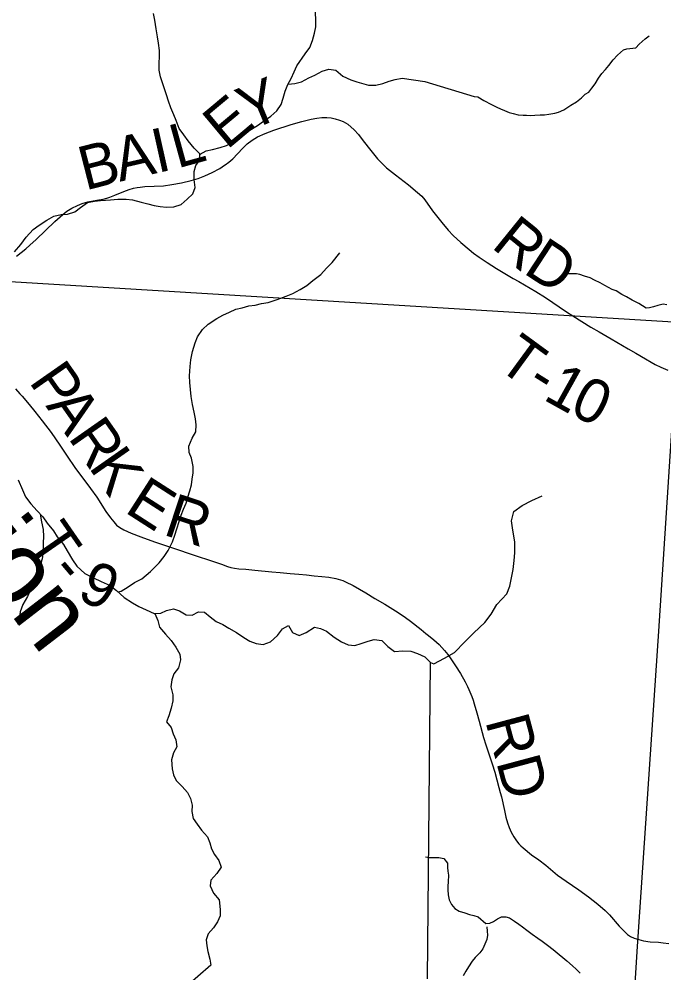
# Model space of a CAD drawing. Extents: x -8.2 to 34, y 0 to 22.
# Drawn here: x 6.76 to 7.595, y 18.744 to 19.98 of the extents above; entities that cross this region are included whole.
import ezdxf

# ---------------------------------------------------------------- set-up
doc = ezdxf.new("R2010")
doc.units = 0
for name, color, linetype in [('GM_X_Corporation', 7, 'Continuous'), ('GM_X_Minor_River', 7, 'Continuous'), ('GM_X_Minor_River_Text', 7, 'Continuous'), ('GM_X_Township_Road', 7, 'Continuous'), ('GM_X_Township_Road_Text', 7, 'Continuous')]:
    doc.layers.add(name, color=color, linetype=linetype)

msp = doc.modelspace()

# ---------------------------------------------------------------- linework, layer by layer
at = {"layer": 'GM_X_Corporation'}
for points in [[(6.6629, 20.6653), (7.6877, 20.6096), (7.6147, 19.5864), (6.5914, 19.6487)], [(7.6147, 19.5864), (8.6299, 19.5206), (8.6049, 19.1351), (8.5816, 18.7383), (8.5636, 18.5025), (7.9912, 18.537), (7.548, 18.5656), (7.5613, 18.7777), (7.5889, 19.1864)]]:
    msp.add_lwpolyline(points, close=True, dxfattribs=at)
at = {"layer": 'GM_X_Minor_River'}
for points in [[(6.9942, 19.8024), (6.9947, 19.8048), (7.0023, 19.809), (7.0106, 19.8109), (7.0205, 19.8133), (7.0285, 19.816), (7.0406, 19.8225), (7.0485, 19.829), (7.0588, 19.8359), (7.069, 19.842), (7.0766, 19.8473), (7.086, 19.8538), (7.094, 19.8611), (7.0993, 19.8691), (7.1023, 19.8775), (7.1045, 19.8862), (7.1082, 19.895), (7.1124, 19.903), (7.1165, 19.9113), (7.1199, 19.9193), (7.1304, 19.9346), (7.1365, 19.943), (7.1402, 19.9521), (7.1428, 19.9616), (7.1443, 19.9696), (7.1441, 19.9969)], [(6.754, 19.6782), (6.7623, 19.6877), (6.7691, 19.6972), (6.7782, 19.7072), (6.7861, 19.7125), (6.796, 19.719), (6.8051, 19.7244), (6.8145, 19.7267), (6.8225, 19.7271), (6.832, 19.7299), (6.8396, 19.7356), (6.8487, 19.7421), (6.8578, 19.744), (6.8654, 19.7445), (6.8783, 19.7457), (6.8878, 19.7465), (6.8988, 19.7465), (6.9068, 19.7454), (6.9179, 19.7425), (6.9266, 19.7402), (6.935, 19.7384), (6.9426, 19.7369), (6.951, 19.7362), (6.9605, 19.7366), (6.97, 19.7393), (6.9775, 19.7462), (6.9851, 19.7534), (6.9881, 19.7614), (6.9869, 19.7721), (6.9868, 19.7823), (6.9887, 19.7899), (6.994, 19.7975), (6.9943, 19.8051), (6.9867, 19.8127), (6.979, 19.8218), (6.9733, 19.8297), (6.9675, 19.838), (6.9636, 19.8483), (6.9606, 19.8558), (6.9567, 19.8649), (6.9536, 19.8733), (6.9509, 19.8816), (6.9482, 19.8892), (6.9459, 19.8971), (6.9432, 19.9051), (6.9416, 19.9135), (6.9412, 19.9229), (6.9419, 19.9309), (6.9418, 19.9393), (6.9406, 19.9488), (6.9391, 19.9567), (6.9375, 19.967), (6.9359, 19.9783), (6.9339, 19.9871)], [(7.2858, 19.8988), (7.3494, 19.8794), (7.3543, 19.879), (7.3623, 19.8742), (7.3719, 19.8693), (7.3791, 19.8656), (7.3837, 19.8633), (7.389, 19.8615), (7.3948, 19.8589), (7.4001, 19.8574), (7.4066, 19.8556), (7.413, 19.8553), (7.4176, 19.8553), (7.4225, 19.855), (7.4282, 19.8554), (7.435, 19.8558), (7.4407, 19.8559), (7.4464, 19.8567), (7.454, 19.8579), (7.4589, 19.8591), (7.4657, 19.8622), (7.4747, 19.8684), (7.4823, 19.8726), (7.4887, 19.8776), (7.4936, 19.8826), (7.4981, 19.8853), (7.5022, 19.8903), (7.5063, 19.896), (7.5108, 19.9033), (7.5149, 19.9094), (7.5198, 19.9144), (7.5243, 19.9198), (7.5299, 19.927), (7.5355, 19.9332), (7.5431, 19.9401), (7.5476, 19.9413), (7.559, 19.9425), (7.5635, 19.9475), (7.571, 19.9544), (7.5763, 19.9583)], [(7.1084, 19.8953), (7.1174, 19.8962), (7.1257, 19.8985), (7.1352, 19.9035), (7.1431, 19.9073), (7.1526, 19.9123), (7.1614, 19.915), (7.1705, 19.9135), (7.1793, 19.906), (7.1896, 19.9011), (7.1976, 19.8985), (7.2128, 19.894), (7.2223, 19.8941), (7.2314, 19.8964), (7.2394, 19.8995), (7.2474, 19.9014), (7.2561, 19.9034), (7.2858, 19.8988)], [(6.8878, 19.2377), (6.8923, 19.2385), (6.9014, 19.2438), (6.9093, 19.2496), (6.9188, 19.2542), (6.9302, 19.2637), (6.9415, 19.2752), (6.9479, 19.2832), (6.9532, 19.2912), (6.9585, 19.3022), (6.9618, 19.311), (6.9644, 19.319), (6.9674, 19.3285), (6.97, 19.3368), (6.973, 19.3448), (6.9764, 19.3524), (6.9787, 19.3604), (6.9813, 19.3684), (6.9831, 19.376), (6.9842, 19.3836), (6.9853, 19.3916), (6.9856, 19.4), (6.9833, 19.4106), (6.9802, 19.4181), (6.9798, 19.4261), (6.9843, 19.4368), (6.9888, 19.4448), (6.9895, 19.4539), (6.9883, 19.4619), (6.9868, 19.4702), (6.9848, 19.4801), (6.9828, 19.4907), (6.9812, 19.5089), (6.9808, 19.5176), (6.9815, 19.5294), (6.9826, 19.5381), (6.9848, 19.5488), (6.9881, 19.5602), (6.9911, 19.5682), (6.9975, 19.5777), (7.0051, 19.5842), (7.0161, 19.5919), (7.0237, 19.5961), (7.0324, 19.5999), (7.0407, 19.6038), (7.0491, 19.6057), (7.0578, 19.608), (7.0658, 19.6092), (7.0742, 19.6112), (7.0825, 19.6127), (7.0943, 19.6162), (7.106, 19.6208), (7.1144, 19.6243), (7.1242, 19.6293), (7.1326, 19.6346), (7.1405, 19.6411), (7.1511, 19.6488), (7.1583, 19.6568), (7.1655, 19.6644), (7.1757, 19.677)], [(7.5993, 19.6096), (7.5943, 19.6103), (7.5875, 19.6084), (7.5819, 19.6068), (7.5769, 19.6056), (7.5724, 19.6052), (7.5628, 19.6112), (7.5544, 19.6157), (7.5472, 19.6198), (7.5411, 19.6227), (7.5334, 19.6276), (7.5285, 19.6295), (7.5189, 19.6347), (7.5128, 19.6381), (7.5056, 19.6414), (7.4999, 19.6444), (7.4926, 19.6466), (7.4865, 19.6488), (7.482, 19.6495), (7.477, 19.6495), (7.471, 19.6498), (7.4638, 19.6486)], [(6.7588, 19.3828), (6.7645, 19.3699), (6.7684, 19.3608), (6.7749, 19.3514), (6.7833, 19.3423), (6.7906, 19.3347), (6.7963, 19.3264), (6.8044, 19.3166), (6.8094, 19.3086), (6.8174, 19.2988), (6.822, 19.2905), (6.8289, 19.2788), (6.8347, 19.2708), (6.845, 19.2614), (6.8561, 19.2557), (6.8664, 19.2509), (6.8778, 19.2456), (6.8862, 19.2392), (6.8961, 19.2301), (6.9068, 19.2234), (6.9152, 19.2185), (6.9244, 19.2143), (6.935, 19.2095), (6.9434, 19.2099), (6.951, 19.2133), (6.9601, 19.2153), (6.9677, 19.213), (6.9765, 19.2078), (6.9841, 19.2074), (6.9924, 19.2117), (7.0001, 19.2113), (7.0077, 19.2049), (7.0153, 19.1989), (7.0241, 19.1951), (7.0317, 19.1906), (7.0417, 19.1846), (7.0512, 19.1782), (7.0588, 19.1737), (7.0672, 19.1707), (7.0763, 19.1692), (7.0858, 19.1727), (7.0949, 19.1807), (7.1013, 19.1895), (7.1089, 19.1937), (7.1143, 19.1846), (7.1227, 19.1808), (7.1321, 19.1847), (7.1428, 19.1916), (7.1504, 19.1901), (7.1584, 19.1867), (7.1683, 19.1788), (7.1778, 19.1728), (7.1862, 19.169), (7.195, 19.1679), (7.2033, 19.1706), (7.2124, 19.1737), (7.22, 19.1757), (7.2299, 19.1746), (7.2376, 19.1666), (7.2464, 19.1602), (7.257, 19.1611), (7.2676, 19.1607), (7.276, 19.1574), (7.2856, 19.1532), (7.2932, 19.1457)], [(7.289, 18.736), (7.2932, 19.1457), (7.2972, 19.1443), (7.311, 19.1517), (7.324, 19.1587), (7.3375, 19.1729), (7.3491, 19.1845), (7.3633, 19.1979), (7.3718, 19.2084), (7.3789, 19.2209), (7.392, 19.2347), (7.3959, 19.2449), (7.4001, 19.2665), (7.4014, 19.2779), (7.4023, 19.2881), (7.4025, 19.3022), (7.3997, 19.3174), (7.398, 19.3296), (7.4008, 19.3418), (7.4116, 19.3492), (7.4242, 19.3558), (7.4376, 19.3621)], [(6.7874, 19.3381), (6.7891, 19.3283), (6.7911, 19.3184), (6.7915, 19.3093), (6.7912, 19.301), (6.7909, 19.2899), (6.7898, 19.2801), (6.7857, 19.2679), (6.783, 19.2584), (6.7801, 19.2493), (6.7748, 19.2401), (6.7707, 19.2314), (6.7646, 19.2211), (6.7613, 19.2116), (6.7602, 19.2036), (6.7579, 19.1952)], [(6.9357, 19.2095), (6.9397, 19.2004), (6.942, 19.1916), (6.9496, 19.1826), (6.9569, 19.1743), (6.9631, 19.1656), (6.9681, 19.1569), (6.9692, 19.1493), (6.9663, 19.139), (6.9606, 19.1314), (6.9576, 19.1234), (6.9565, 19.1143), (6.9589, 19.104), (6.9593, 19.0964), (6.9571, 19.0869), (6.9541, 19.0767), (6.9511, 19.0691), (6.9568, 19.0615), (6.9595, 19.0535), (6.963, 19.0456), (6.9642, 19.0365), (6.96, 19.0289), (6.9574, 19.0197), (6.9583, 19.008), (6.9598, 19.0004), (6.9633, 18.9928), (6.971, 18.9852), (6.9782, 18.9773), (6.9821, 18.9697), (6.984, 18.961), (6.9837, 18.9527), (6.9856, 18.9439), (6.9906, 18.9364), (6.9964, 18.9288), (7.004, 18.9201), (7.0071, 18.9122), (7.0091, 18.9046), (7.0133, 18.897), (7.0187, 18.8894), (7.0218, 18.8807), (7.0161, 18.8723), (7.0085, 18.8639), (7.0074, 18.8563), (7.0117, 18.8469), (7.019, 18.8382), (7.0205, 18.8257), (7.0206, 18.8177), (7.0168, 18.8097), (7.0116, 18.8021), (7.0051, 18.7944), (7.0021, 18.7864), (7.003, 18.7789), (7.0045, 18.7713), (7.0069, 18.7614), (7.0084, 18.7538), (6.9745, 18.7244)], [(7.2865, 18.8941), (7.2914, 18.8934), (7.2967, 18.8931), (7.3036, 18.8932), (7.3104, 18.8917), (7.315, 18.886), (7.3151, 18.8803), (7.3155, 18.8754), (7.3163, 18.8701), (7.316, 18.8617), (7.3153, 18.856), (7.3154, 18.8511), (7.3158, 18.8446), (7.3174, 18.8382), (7.3201, 18.8321), (7.3244, 18.8272), (7.3301, 18.8235), (7.3373, 18.8213), (7.3434, 18.8194), (7.3491, 18.818), (7.3549, 18.8161), (7.3648, 18.8078), (7.3697, 18.8079), (7.3746, 18.8102), (7.3799, 18.8137), (7.3848, 18.8164), (7.3905, 18.8165), (7.3955, 18.815), (7.402, 18.8105), (7.4073, 18.8067), (7.4123, 18.8034), (7.418, 18.7989), (7.4249, 18.794), (7.4322, 18.7887), (7.4375, 18.7846), (7.4448, 18.7797), (7.4521, 18.7741), (7.4597, 18.7673), (7.4647, 18.7636), (7.4697, 18.7591), (7.477, 18.7527), (7.4819, 18.7485), (7.4869, 18.7433)], [(7.366, 18.8033), (7.3664, 18.7976), (7.3669, 18.7927), (7.3662, 18.787), (7.361, 18.7748), (7.3569, 18.7698), (7.3508, 18.7636), (7.3471, 18.7587), (7.3422, 18.7514), (7.3389, 18.746), (7.3352, 18.7399)]]:
    msp.add_lwpolyline(points, dxfattribs=at)
at = {"layer": 'GM_X_Township_Road'}
for points in [[(7.027, 19.7909), (7.0317, 19.7944), (7.0368, 19.7988), (7.0495, 19.8119), (7.0556, 19.818), (7.0621, 19.8229), (7.0688, 19.827), (7.0788, 19.8314), (7.0901, 19.8359), (7.1123, 19.8432), (7.1264, 19.8472), (7.1383, 19.8501), (7.1455, 19.8514), (7.1522, 19.8522), (7.1586, 19.8524), (7.1644, 19.8518), (7.1696, 19.8507), (7.175, 19.849), (7.1799, 19.8469), (7.1858, 19.8434), (7.194, 19.8362), (7.1997, 19.8302), (7.2046, 19.8239), (7.2124, 19.8139), (7.2245, 19.7989), (7.2294, 19.7933), (7.2362, 19.787), (7.2475, 19.7781), (7.2645, 19.7652), (7.2763, 19.7552), (7.2816, 19.7501), (7.2856, 19.7454), (7.2958, 19.7314), (7.3076, 19.7162), (7.316, 19.7062), (7.3223, 19.6995), (7.3322, 19.6901), (7.3429, 19.6811), (7.3486, 19.6764), (7.356, 19.6711), (7.36, 19.6685)], [(6.7565, 19.6726), (6.7687, 19.6822), (6.7739, 19.6866), (6.7822, 19.6942), (6.8064, 19.7174), (6.8164, 19.7267), (6.8218, 19.7308), (6.8282, 19.7347), (6.8354, 19.7383), (6.8418, 19.7408), (6.8489, 19.7429), (6.8605, 19.7452), (6.869, 19.7466), (6.8737, 19.7479), (6.8774, 19.7491), (6.884, 19.7514), (6.8957, 19.7565), (6.9025, 19.7588), (6.9082, 19.7606), (6.9128, 19.7617), (6.9168, 19.7621), (6.923, 19.7627), (6.9469, 19.7639), (6.958, 19.7653), (6.9702, 19.7675), (6.9829, 19.7705), (6.9918, 19.7733), (7.0005, 19.7767), (7.01, 19.7811), (7.0199, 19.7863), (7.0262, 19.7903), (7.027, 19.7909)], [(7.36, 19.6685), (7.3664, 19.6643), (7.3785, 19.6565), (7.4003, 19.6435), (7.4073, 19.6395), (7.4294, 19.6268), (7.442, 19.6188), (7.4692, 19.6003), (7.4776, 19.595), (7.5009, 19.5807), (7.5116, 19.5743), (7.5272, 19.5654), (7.5492, 19.5524), (7.559, 19.5467), (7.5717, 19.5395), (7.5789, 19.5352), (7.5843, 19.532), (7.5913, 19.5287), (7.6005, 19.5249)], [(6.7551, 19.5004), (6.761, 19.4941), (6.7639, 19.4909), (6.7728, 19.4805), (6.7802, 19.4713), (6.7899, 19.459), (6.8013, 19.444), (6.8126, 19.4276), (6.8222, 19.4134), (6.8322, 19.3986), (6.8523, 19.3714), (6.8606, 19.3602), (6.8725, 19.3418), (6.8782, 19.3334), (6.8825, 19.3281), (6.8863, 19.3239), (6.8905, 19.3207), (6.8956, 19.3177), (6.9053, 19.3135), (6.9175, 19.3088), (6.9355, 19.3025), (6.9572, 19.295), (6.9895, 19.2843), (7.0079, 19.278), (7.022, 19.2732), (7.0299, 19.2705), (7.0343, 19.2691), (7.0391, 19.2682), (7.0447, 19.2674), (7.0538, 19.2667), (7.0655, 19.2657), (7.0874, 19.2635), (7.0981, 19.2625), (7.1112, 19.2614), (7.1224, 19.2604), (7.1323, 19.2595), (7.1421, 19.2584), (7.152, 19.2575), (7.1613, 19.2563), (7.1704, 19.2546), (7.1793, 19.252), (7.1828, 19.2505), (7.1928, 19.2456), (7.2091, 19.2361), (7.2209, 19.229), (7.2338, 19.2214), (7.251, 19.2105), (7.2606, 19.2042), (7.2671, 19.1995), (7.2809, 19.1888), (7.2871, 19.1837), (7.2905, 19.181), (7.2972, 19.1754), (7.3041, 19.1691), (7.3112, 19.1614), (7.3155, 19.1561), (7.3178, 19.1531), (7.3255, 19.1418), (7.3317, 19.1318), (7.3378, 19.121), (7.3409, 19.1149), (7.3428, 19.1109), (7.3466, 19.1018), (7.3483, 19.0971), (7.3498, 19.0924), (7.3532, 19.0805), (7.3561, 19.0697), (7.3617, 19.0487), (7.3645, 19.0392), (7.3729, 19.0145), (7.3762, 19.0038), (7.3817, 18.9841), (7.3835, 18.9776), (7.385, 18.9716), (7.3888, 18.954), (7.3906, 18.9455), (7.3926, 18.9383), (7.395, 18.932), (7.3975, 18.926), (7.4009, 18.92), (7.4045, 18.9149), (7.4075, 18.9111), (7.4101, 18.9084), (7.4129, 18.9058), (7.4241, 18.8968), (7.4332, 18.89), (7.4423, 18.8831), (7.4576, 18.8705), (7.4631, 18.8664), (7.4687, 18.8626), (7.4851, 18.8513), (7.4977, 18.8422), (7.5099, 18.8325), (7.5192, 18.8244), (7.525, 18.8189), (7.5375, 18.8043), (7.5452, 18.7962), (7.5484, 18.7934), (7.5521, 18.791), (7.5571, 18.7886), (7.563, 18.7867), (7.569, 18.7853), (7.5777, 18.7841), (7.5885, 18.7834), (7.5945, 18.7827), (7.6019, 18.7816)]]:
    msp.add_lwpolyline(points, dxfattribs=at)

# ---------------------------------------------------------------- texts
at = {"layer": 'GM_X_Minor_River_Text'}
msp.add_text('Onion', height=0.0947, rotation=307.6002, dxfattribs=at).set_placement((6.5845, 19.4211))
at = {"layer": 'GM_X_Township_Road_Text'}
for s, height, rotation, p in [('Y', 0.0568, 22.5083, (7.0577, 19.8344)), ('E', 0.0568, 39.9063, (7.029, 19.8095)), ('L', 0.0568, 15.3793, (6.9647, 19.786)), ('A', 0.0568, 12.9954, (6.8903, 19.7689)), ('I', 0.0568, 12.5424, (6.9389, 19.7802)), ('B', 0.0568, 14.3931, (6.8455, 19.7574)), ('R', 0.0568, 321.0415, (7.3704, 19.6845)), ('D', 0.0568, 326.7853, (7.4117, 19.6515)), ('T', 0.0568, 323.8321, (7.377, 19.5292)), ('P', 0.0568, 304.9671, (6.7717, 19.5099)), ('-', 0.0568, 327.7845, (7.4149, 19.5017)), ('1', 0.0568, 330.9074, (7.4375, 19.4875)), ('0', 0.0568, 334.1383, (7.4712, 19.4689)), ('A', 0.0568, 304.9663, (6.7937, 19.4785)), ('R', 0.0568, 304.9663, (6.8224, 19.4375)), ('K', 0.0568, 304.9689, (6.8491, 19.3993)), ('E', 0.0568, 327.3093, (6.8951, 19.3417)), ('R', 0.0568, 341.8344, (6.9451, 19.312)), ('T', 0.0568, 304.7206, (6.7701, 19.3028)), ('-', 0.0568, 310.3135, (6.7979, 19.263)), ('9', 0.0568, 333.8314, (6.833, 19.2297)), ('RD', 0.05682, 284.9947, (7.3637, 19.0703))]:
    msp.add_text(s, height=height, rotation=rotation, dxfattribs=at).set_placement(p)

doc.saveas('drawing.dxf')
